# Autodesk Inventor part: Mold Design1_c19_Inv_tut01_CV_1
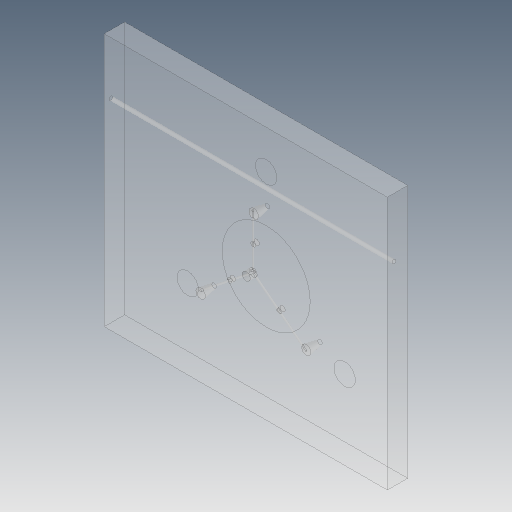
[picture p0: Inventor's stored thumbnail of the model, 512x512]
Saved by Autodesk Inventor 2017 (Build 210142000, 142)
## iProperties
Created: 2016-07
Part Number: Mold Design1_c19_Inv_tut01_CV_1
Material: Generic
Document SubType Name: Modeling
Designer: Sandeep
Density: 1 g/cm^3
Appearance: Default
Author: Sandeep
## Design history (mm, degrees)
node "Mold Design1_c19_Inv_tut01_CV_Base"
feature "Sculpt8"
feature "Sculpt13"
feature "Sculpt14"
feature "Solid1::Mold Design1_c19_Inv_tut01_CV_Base"
tag "TaggingFeature1"
body "Solid1"
feature "Mold Design1_c19_Inv_tut01_CV_Base_Bodies"
feature "Surface8"
body "Srf8"
feature "Surface13"
body "Srf13"
feature "Surface14"
body "Srf14"
